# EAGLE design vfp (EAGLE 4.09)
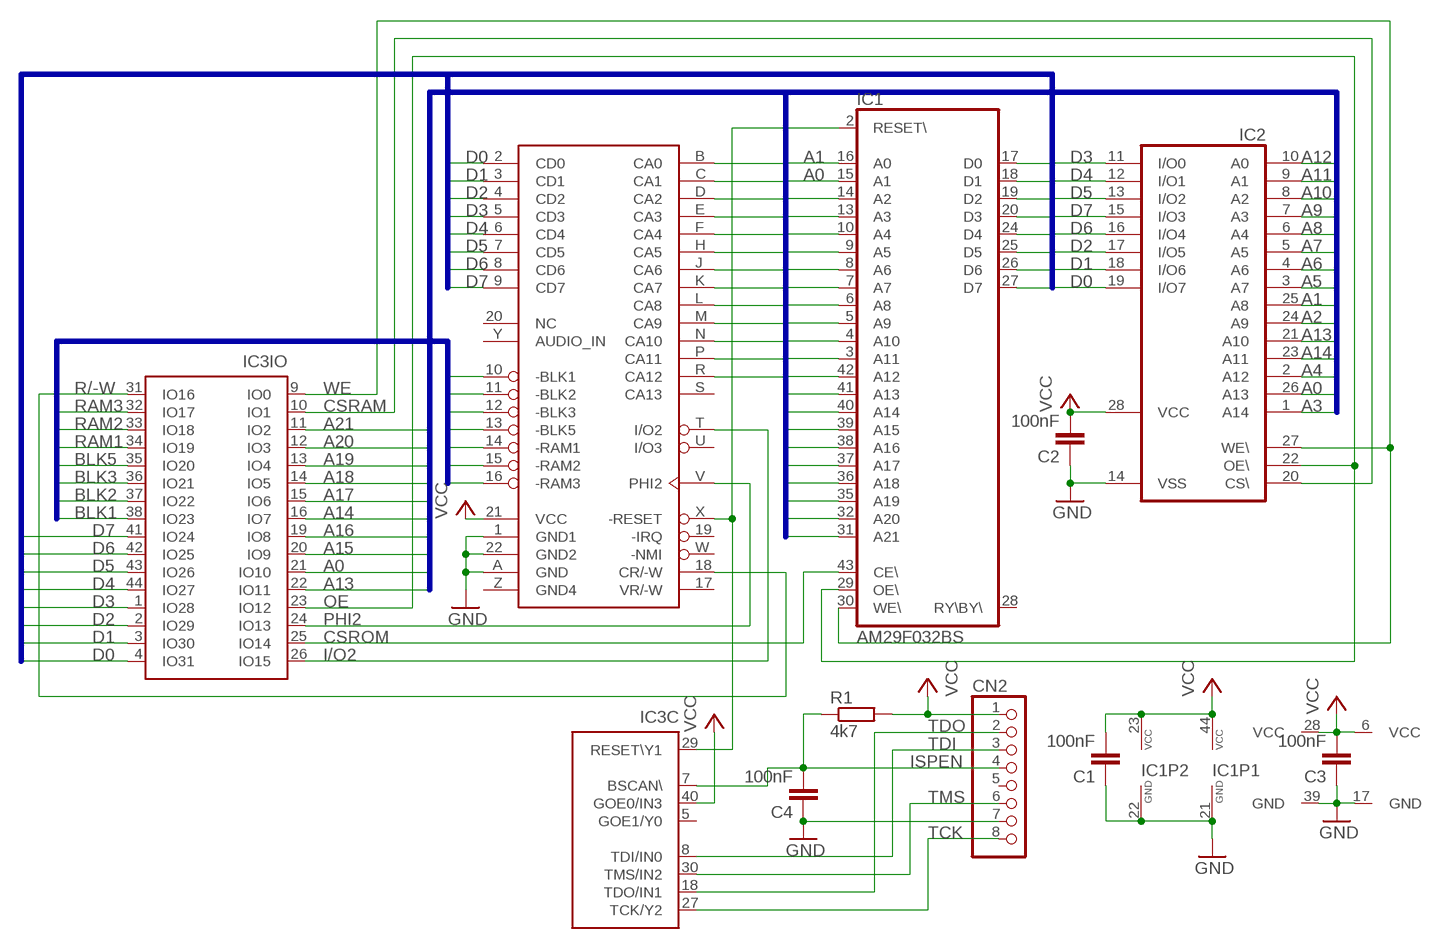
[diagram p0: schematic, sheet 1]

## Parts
C1  100nF  C-EUC0805  [C0805]
C2  100nF  C-EUC0805  [C0805]
C3  100nF  C-EUC0805  [C0805]
C4  100nF  C-EUC0805  [C0805]
CN1  VIC20CART1  [VIC20CART]
CN2  PINHD-1X8  [1X08]
IC1  AM29F032BS  [SO44]
IC2  62256FP  [SO28L]
IC3  2064VET44  [TQFP44]
R1  4k7  R-EU_R0805  [R0805]

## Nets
A0: CN1.B(CA0) IC1.15(A1) IC2.26(A13) IC3.21(IO:IO10)
A1: CN1.C(CA1) IC1.16(A0) IC2.25(A8)
A2: CN1.D(CA2) IC1.14(A2) IC2.24(A9)
A3: CN1.E(CA3) IC1.13(A3) IC2.1(A14)
A4: CN1.F(CA4) IC1.10(A4) IC2.2(A12)
A5: CN1.H(CA5) IC1.9(A5) IC2.3(A7)
A6: CN1.J(CA6) IC1.8(A6) IC2.4(A6)
A7: CN1.K(CA7) IC1.7(A7) IC2.5(A5)
A8: CN1.L(CA8) IC1.6(A8) IC2.6(A4)
A9: CN1.M(CA9) IC1.5(A9) IC2.7(A3)
A10: CN1.N(CA10) IC1.4(A10) IC2.8(A2)
A11: CN1.P(CA11) IC1.3(A11) IC2.9(A1)
A12: CN1.R(CA12) IC1.42(A12) IC2.10(A0)
A13: IC1.41(A13) IC2.21(A10) IC3.22(IO:IO11)
A14: IC1.40(A14) IC2.23(A11) IC3.16(IO:IO7)
A15: IC1.39(A15) IC3.20(IO:IO9)
A16: IC1.38(A16) IC3.19(IO:IO8)
A17: IC1.37(A17) IC3.15(IO:IO6)
A18: IC1.36(A18) IC3.14(IO:IO5)
A19: IC1.35(A19) IC3.13(IO:IO4)
A20: IC1.32(A20) IC3.12(IO:IO3)
A21: IC1.31(A21) IC3.11(IO:IO2)
BLK1: CN1.10(-BLK1) IC3.38(IO:IO23)
BLK2: CN1.11(-BLK2) IC3.37(IO:IO22)
BLK3: CN1.12(-BLK3) IC3.36(IO:IO21)
BLK5: CN1.13(-BLK5) IC3.35(IO:IO20)
CSRAM: IC2.20(CS\) IC3.10(IO:IO1)
CSROM: IC1.43(CE\) IC3.25(IO:IO14)
D0: CN1.2(CD0) IC1.17(D0) IC2.19(I/O7) IC3.4(IO:IO31)
D1: CN1.3(CD1) IC1.18(D1) IC2.18(I/O6) IC3.3(IO:IO30)
D2: CN1.4(CD2) IC1.19(D2) IC2.17(I/O5) IC3.2(IO:IO29)
D3: CN1.5(CD3) IC1.20(D3) IC2.11(I/O0) IC3.1(IO:IO28)
D4: CN1.6(CD4) IC1.24(D4) IC2.12(I/O1) IC3.44(IO:IO27)
D5: CN1.7(CD5) IC1.25(D5) IC2.13(I/O2) IC3.43(IO:IO26)
D6: CN1.8(CD6) IC1.26(D6) IC2.16(I/O4) IC3.42(IO:IO25)
D7: CN1.9(CD7) IC1.27(D7) IC2.15(I/O3) IC3.41(IO:IO24)
GND: C1.1 C2.1 C3.1 C4.1 CN1.1(GND1) CN1.22(GND2) CN1.A(GND) CN2.7 IC1.21(GND) IC1.22(GND) IC2.14(VSS) IC3.17(GND) IC3.39(GND)
I/O2: CN1.T(I/O2) IC3.26(IO:IO15)
ISPEN: C4.2 CN2.4 IC3.7(C:BSCAN\) R1.1
OE: IC1.29(OE\) IC2.22(OE\) IC3.23(IO:IO12)
PHI2: CN1.V(PHI2) IC3.24(IO:IO13)
R/-W: CN1.18(CR/-W) IC3.31(IO:IO16)
RAM1: CN1.14(-RAM1) IC3.34(IO:IO19)
RAM2: CN1.15(-RAM2) IC3.33(IO:IO18)
RAM3: CN1.16(-RAM3) IC3.32(IO:IO17)
RESET: CN1.X(-RESET) IC1.2(RESET\) IC3.29(C:RESET\Y1)
TCK: CN2.8 IC3.27(C:TCK/Y2)
TDI: CN2.3 IC3.8(C:TDI/IN0)
TDO: CN2.2 IC3.18(C:TDO/IN1)
TMS: CN2.6 IC3.30(C:TMS/IN2)
VCC: C1.2 C2.2 C3.2 CN1.21(VCC) CN2.1 IC1.23(VCC) IC1.44(VCC) IC2.28(VCC) IC3.6(V1:VCC) IC3.28(V2:VCC) IC3.40(C:GOE0/IN3) R1.2
WE: IC1.30(WE\) IC2.27(WE\) IC3.9(IO:IO0)
Unconnected: CN1.17(VR/-W) CN1.19(-IRQ) CN1.20(NC) CN1.S(CA13) CN1.U(I/O3) CN1.W(-NMI) CN1.Y(AUDIO_IN) CN1.Z(GND4) CN2.5 IC1.1(NC) IC1.28(RY\BY\) IC3.5(C:GOE1/Y0)

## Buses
A[0..21]
D[0..7]
BLK[1..3],BLK5,RAM[1..3]

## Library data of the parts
C1-C4 = rcl:C-EU: CAPACITOR, European symbol
CN1 = vic-20:VIC20CART*: VIC-20 cartridge port connector
CN2 = pinhead:PINHD-1X8: PIN HEADER
IC1 = am29-memory:AM29F032B: 32 megabit (4Mb×8) 5-volt Flash ROM
IC2 = memory-hitachi:62256FP: MEMORY
IC3 = lattice:2064VET44: LATTICE PROGRAMMABLE DEVICE
R1 = rcl:R-EU_: RESISTOR, European symbol

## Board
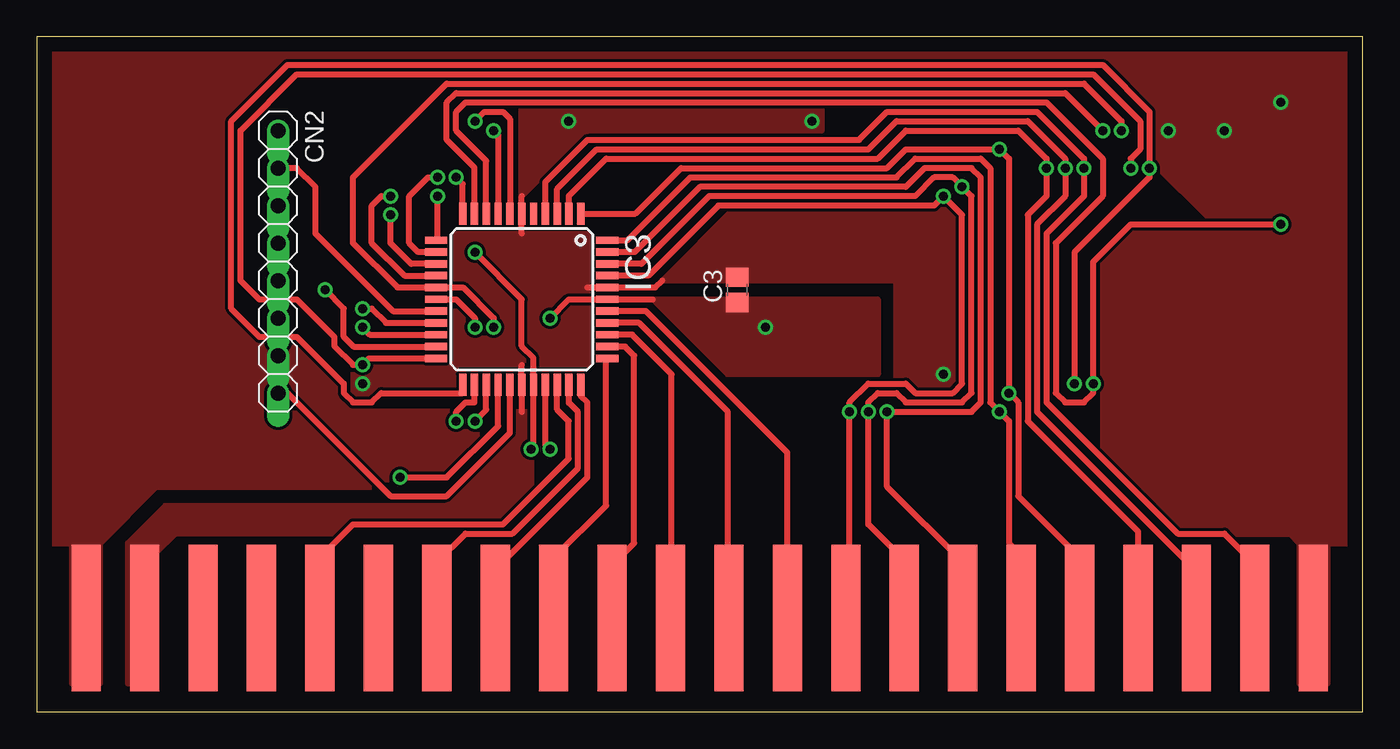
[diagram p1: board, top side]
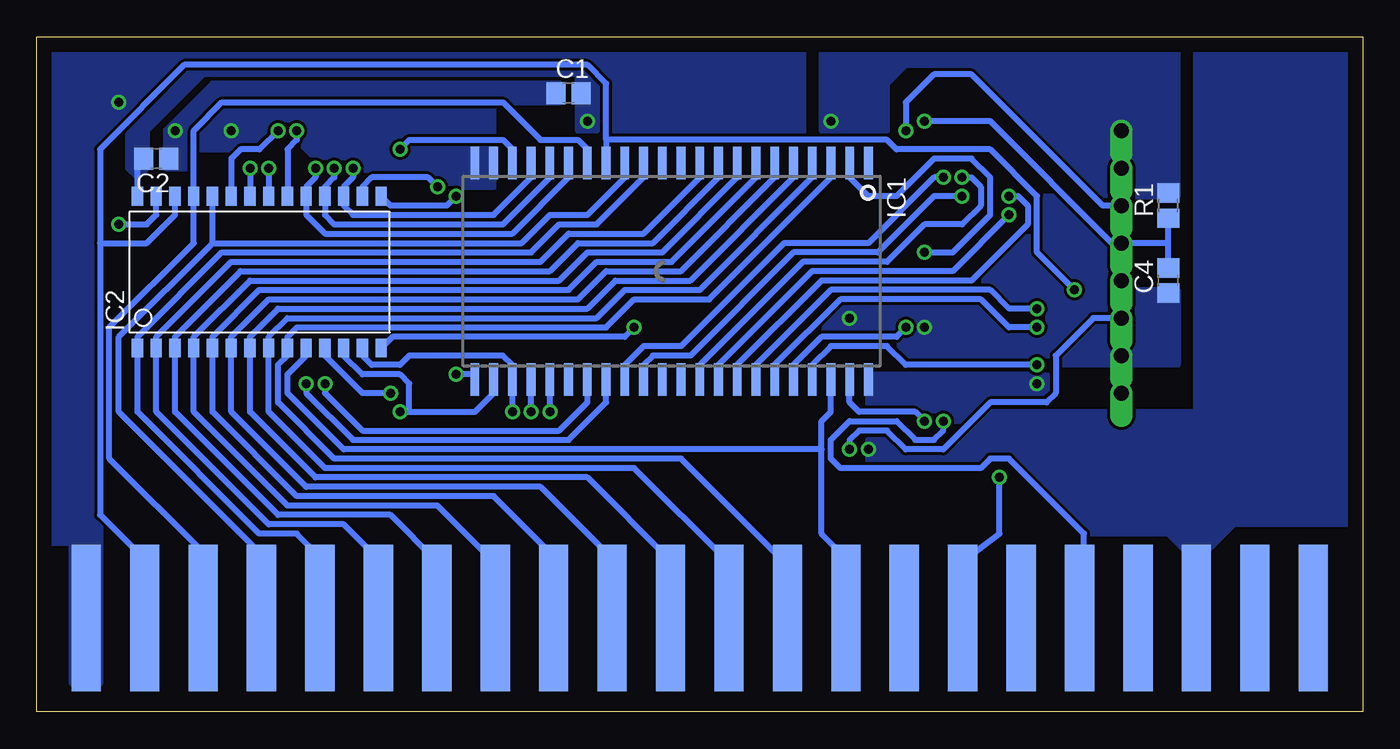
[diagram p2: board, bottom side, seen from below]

Size 89.84 x 45.71 mm. Coordinates in mm from the lower left corner, seen from the top.
Outline: 0,0 89.84,0 89.84,45.71 0,45.71 0,0
Copper layers used: Top, Bottom

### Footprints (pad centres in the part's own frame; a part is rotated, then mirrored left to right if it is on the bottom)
C0805 = smd 1.3 x 1.5: 1 -0.85,0; 2 0.85,0
VIC20CART = smd 1.98 x 9.9: 1 -41.58,0; 2 -37.62,0; 3 -33.66,0; 4 -29.7,0; 5 -25.74,0; 6 -21.78,0; 7 -17.82,0; 8 -13.86,0; 9 -9.9,0; 10 -5.94,0; 11 -1.98,0; 12 1.98,0; 13 5.94,0; 14 9.9,0; 15 13.86,0; 16 17.82,0; 17 21.78,0; 18 25.74,0; 19 29.7,0; 20 33.66,0; 21 37.62,0; 22 41.58,0 | smd 1.98 x 9.9 bottom: A -41.58,0; B -37.62,0; C -33.66,0; D -29.7,0; E -25.74,0; F -21.78,0; H -17.82,0; J -13.86,0; K -9.9,0; L -5.94,0; M -1.98,0; N 1.98,0; P 5.94,0; R 9.9,0; S 13.86,0; T 17.82,0; U 21.78,0; V 25.74,0; W 29.7,0; X 33.66,0; Y 37.62,0; Z 41.58,0
1X08 = drill 1.016 offset: 1 -8.89,0; 2 -6.35,0; 3 -3.81,0; 4 -1.27,0; 5 1.27,0; 6 3.81,0; 7 6.35,0; 8 8.89,0
SO44 = smd 0.6 x 2.2: 1 -13.335,-7.34; 2 -12.065,-7.34; 3 -10.795,-7.34; 4 -9.525,-7.34; 5 -8.255,-7.34; 6 -6.985,-7.34; 7 -5.715,-7.34; 8 -4.445,-7.34; 9 -3.175,-7.34; 10 -1.905,-7.34; 11 -0.635,-7.34; 12 0.635,-7.34; 13 1.905,-7.34; 14 3.175,-7.34; 15 4.445,-7.34; 16 5.715,-7.34; 17 6.985,-7.34; 18 8.255,-7.34; 19 9.525,-7.34; 20 10.795,-7.34; 21 12.065,-7.34; 22 13.335,-7.34; 23 13.335,7.34; 24 12.065,7.34; 25 10.795,7.34; 26 9.525,7.34; 27 8.255,7.34; 28 6.985,7.34; 29 5.715,7.34; 30 4.445,7.34; 31 3.175,7.34; 32 1.905,7.34; 33 0.635,7.34; 34 -0.635,7.34; 35 -1.905,7.34; 36 -3.175,7.34; 37 -4.445,7.34; 38 -5.715,7.34; 39 -6.985,7.34; 40 -8.255,7.34; 41 -9.525,7.34; 42 -10.795,7.34; 43 -12.065,7.34; 44 -13.335,7.34
SO28L = smd 0.762 x 1.27: 1 -7.62,-5.207; 2 -6.35,-5.207; 3 -5.08,-5.207; 4 -3.81,-5.207; 5 -2.54,-5.207; 6 -1.27,-5.207; 7 0,-5.207; 8 1.27,-5.207; 9 2.54,-5.207; 10 3.81,-5.207; 11 5.08,-5.207; 12 6.35,-5.207; 13 7.62,-5.207; 14 8.89,-5.207; 15 8.89,5.08; 16 7.62,5.08; 17 6.35,5.08; 18 5.08,5.08; 19 3.81,5.08; 20 2.54,5.08; 21 1.27,5.08; 22 0,5.08; 23 -1.27,5.08; 24 -2.54,5.08; 25 -3.81,5.08; 26 -5.08,5.08; 27 -6.35,5.08; 28 -7.62,5.08
TQFP44 = smd 1.5 x 0.5: 1 -5.8,4; 2 -5.8,3.2; 3 -5.8,2.4; 4 -5.8,1.6; 5 -5.8,0.8; 6 -5.8,0; 7 -5.8,-0.8; 8 -5.8,-1.6; 9 -5.8,-2.4; 10 -5.8,-3.2; 11 -5.8,-4; 23 5.8,-4; 24 5.8,-3.2; 25 5.8,-2.4; 26 5.8,-1.6; 27 5.8,-0.8; 28 5.8,0; 29 5.8,0.8; 30 5.8,1.6; 31 5.8,2.4; 32 5.8,3.2; 33 5.8,4 | smd 0.5 x 1.5: 12 -4,-5.8; 13 -3.2,-5.8; 14 -2.4,-5.8; 15 -1.6,-5.8; 16 -0.8,-5.8; 17 0,-5.8; 18 0.8,-5.8; 19 1.6,-5.8; 20 2.4,-5.8; 21 3.2,-5.8; 22 4,-5.8; 34 4,5.8; 35 3.2,5.8; 36 2.4,5.8; 37 1.6,5.8; 38 0.8,5.8; 39 0,5.8; 40 -0.8,5.8; 41 -1.6,5.8; 42 -2.4,5.8; 43 -3.2,5.8; 44 -4,5.8
R0805 = smd 1.3 x 1.5: 1 -0.85,0; 2 0.85,0

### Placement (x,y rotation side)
C1  53.81,41.91 0 bottom
C2  81.75,37.46 180 bottom
C3  47.46,28.57 90 top
C4  13.17,29.2 90 bottom
CN1  44.92,6.35 180 top
CN2  16.35,30.47 270 top
IC1  46.83,29.84 180 bottom
IC2  75.4,29.84 0 bottom
IC3  32.86,27.93 270 top
R1  13.17,34.29 90 bottom

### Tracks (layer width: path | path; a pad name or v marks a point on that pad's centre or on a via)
A0  (via drill 0.61)
  Top 0.406: v19.52,28.57 20.79,27.3 20.79,25.39 21.45,24.73 IC3.21
  Bottom 0.406: IC2.26 80.48,33.65 82.38,31.75 85.56,31.75 | CN1.B 82.54,10.31 85.56,13.33 85.56,31.75 | 85.56,31.75 85.56,38.1 79.84,43.81 52.54,43.81 51.27,42.54 51.27,38.73 | 51.27,38.73 IC1.15 | 51.27,38.73 32.22,38.73 31.59,38.1 25.23,38.1 22.06,34.92 22.06,31.11 v19.52,28.57
A1
  Bottom 0.406: CN1.C 78.58,10.79 84.92,17.14 84.92,26.03 79.21,31.75 IC2.25 79.21,39.37 77.3,41.27 58.26,41.27 55.72,38.73 53.18,38.73 52.54,38.1 IC1.16
A2
  Bottom 0.406: CN1.D 74.62,10.64 84.29,20.32 84.29,25.39 77.94,31.75 | 77.94,31.75 IC2.24 | IC1.14 50,36.19 52.54,33.65 55.08,33.65 56.98,31.75 77.94,31.75
A3
  Bottom 0.406: IC1.13 48.73,36.19 51.91,33.02 54.45,33.02 56.35,31.11 77.3,31.11 83.02,25.39 IC2.1 83.02,20.32 74.77,12.06 72.22,12.06 70.66,10.5 CN1.E
A4
  Bottom 0.406: CN1.F 66.7,10.34 69.05,12.7 74.13,12.7 81.75,20.32 IC2.2 81.75,25.39 76.67,30.47 55.72,30.47 53.81,32.38 48.73,32.38 44.92,36.19 IC1.10
A5
  Bottom 0.406: CN1.H 62.74,10.2 65.88,13.33 73.49,13.33 80.48,20.32 IC2.3 80.48,25.39 76.03,29.84 55.08,29.84 53.18,31.75 48.09,31.75 43.65,36.19 IC1.9
A6
  Bottom 0.406: CN1.J 58.78,10.04 62.7,13.96 72.86,13.96 79.21,20.32 IC2.4 79.21,25.39 75.4,29.2 54.45,29.2 52.54,31.11 47.46,31.11 42.38,36.19 IC1.8
A7
  Bottom 0.406: CN1.K 54.82,10.53 58.89,14.6 72.22,14.6 77.94,20.32 IC2.5 77.94,25.39 74.77,28.57 53.81,28.57 51.91,30.47 46.83,30.47 41.11,36.19 IC1.7
A8
  Bottom 0.406: CN1.L 50.86,10.38 55.72,15.23 71.59,15.23 76.67,20.32 IC2.6 76.67,25.39 74.13,27.93 53.18,27.93 51.27,29.84 46.19,29.84 39.84,36.19 IC1.6
A9
  Bottom 0.406: CN1.M 46.9,10.23 52.54,15.87 70.95,15.87 75.4,20.32 IC2.7 75.4,25.39 73.49,27.3 52.54,27.3 50.63,29.2 45.55,29.2 38.57,36.19 IC1.5
A10
  Bottom 0.406: CN1.N 42.94,10.08 49.37,16.5 70.32,16.5 74.13,20.32 IC2.8 74.13,25.39 72.86,26.66 51.91,26.66 50,28.57 44.92,28.57 37.3,36.19 IC1.4
A11
  Bottom 0.406: CN1.P 38.98,9.93 46.19,17.14 69.68,17.14 73.49,20.95 73.49,23.49 72.86,24.12 IC2.9 72.86,25.39 72.22,26.03 51.27,26.03 49.37,27.93 44.29,27.93 36.03,36.19 IC1.3
A12
  Bottom 0.406: CN1.R 35.02,10.41 36.66,12.06 36.66,17.77 | 36.66,17.77 69.05,17.77 72.86,21.59 72.86,22.86 71.59,24.12 IC2.10 | IC1.42 36.03,20.32 36.66,19.68 36.66,17.77
A13  (via drill 0.61)
  Top 0.406: v74.13,36.83 74.13,37.46 74.77,38.1 74.77,40 71.59,43.18 17.62,43.18 13.81,39.37 13.81,29.2 15.08,27.93 17.62,27.93 20.16,25.39 20.16,24.76 21.43,23.49 v22.06,23.49 22.51,23.93 IC3.22
  Bottom 0.406: v74.13,36.83 IC2.21 | IC1.41 37.3,23.49 36.03,24.76 32.22,24.76 30.95,23.49 v22.06,23.49
A14  (via drill 0.61)
  Top 0.406: v73.49,39.37 73.49,40 70.95,42.54 27.78,42.54 21.43,36.19 21.43,31.75 24.44,28.73 IC3.16 28.88,28.73 30.95,26.66 v30.95,26.03
  Bottom 0.406: IC2.23 76.67,37.46 76.03,38.1 74.77,38.1 v73.49,39.37 | v30.95,26.03 31.59,25.39 36.66,25.39 38.57,23.49 IC1.40
A15  (via drill 0.61)
  Top 0.406: IC3.20 22.55,25.54 v22.06,26.03
  Bottom 0.406: IC1.39 39.84,23.49 35.4,27.93 25.87,27.93 23.96,26.03 v22.06,26.03
A16  (via drill 0.61)
  Top 0.406: IC3.19 23.66,26.34 22.7,27.3 v22.06,27.3
  Bottom 0.406: IC1.38 41.11,23.49 36.03,28.57 25.23,28.57 23.96,27.3 v22.06,27.3
A17  (via drill 0.61)
  Top 0.406: IC3.15 24.91,29.54 22.7,31.75 22.7,34.29 23.33,34.92 v23.96,34.92
  Bottom 0.406: IC1.37 42.38,23.49 36.66,29.2 26.51,29.2 22.7,33.02 22.7,34.29 23.33,34.92 v23.96,34.92
A18  (via drill 0.61)
  Top 0.406: IC3.14 25.38,30.34 23.96,31.75 v23.96,33.65
  Bottom 0.406: IC1.36 43.65,23.49 37.3,29.84 27.78,29.84 v23.96,33.65
A19  (via drill 0.61)
  Top 0.406: IC3.13 25.85,31.13 25.23,31.75 25.23,34.92 26.51,36.19 v27.14,36.19
  Bottom 0.406: v27.14,36.19 26.51,36.19 25.87,35.55 25.87,34.29 27.14,33.02 29.68,33.02 32.22,30.47 37.94,30.47 44.92,23.49 IC1.35
A20  (via drill 0.61)
  Top 0.406: IC3.12 27.14,31.93 v27.14,34.92
  Bottom 0.406: IC1.32 48.73,23.49 48.09,24.12 45.55,24.12 38.57,31.11 32.86,31.11 29.05,34.92 v27.14,34.92
A21  (via drill 0.61)
  Top 0.406: IC3.11 28.86,35.75 v28.41,36.19
  Bottom 0.406: IC1.31 50,23.49 48.73,24.76 46.19,24.76 39.2,31.75 33.49,31.75 29.05,36.19 v28.41,36.19
BLK1
  Top 0.406: CN1.10 50.86,17.55 41.27,27.13 IC3.38
BLK2
  Top 0.406: CN1.11 46.83,6.35 46.83,20.32 40.8,26.34 IC3.37
BLK3
  Top 0.406: IC3.36 40.34,25.54 43.02,22.86 43.02,6.35 CN1.12
BLK5
  Top 0.406: CN1.13 38.98,9.93 40.48,11.43 40.48,24.12 39.87,24.73 IC3.35
CSRAM  (via drill 0.61)
  Top 0.406: v72.22,39.37 69.68,41.91 28.41,41.91 27.78,41.27 27.78,38.73 29.66,36.85 IC3.10
  Bottom 0.406: v72.22,39.37 72.22,38.73 72.86,38.1 IC2.20
CSROM  (via drill 0.61)
  Top 0.406: IC3.25 30.46,20.46 v29.68,19.68
  Bottom 0.406: IC1.43 34.76,20.95 34.12,20.32 30.32,20.32 v29.68,19.68
D0  (via drill 0.61)
  Top 0.406: CN1.2 82.54,10 80.48,12.06 77.3,12.06 68.41,20.95 68.41,32.38 70.95,34.92 v70.95,36.83 70.95,37.46 67.78,40.64 57.62,40.64 55.72,38.73 37.3,38.73 34.45,35.88 IC3.4
  Bottom 0.406: v70.95,36.83 70.95,36.19 71.59,35.55 IC2.19 71.59,33.65 70.32,32.38 57.62,32.38 53.81,36.19 IC1.17
D1  (via drill 0.61)
  Top 0.406: CN1.3 78.58,8.25 78.57,8.25 78.57,9.52 67.78,20.32 67.78,33.02 69.68,34.92 v69.68,36.83 69.68,37.46 67.14,40 58.26,40 56.35,38.1 37.94,38.1 35.26,35.41 IC3.3
  Bottom 0.406: v69.68,36.83 69.68,36.19 70.32,35.55 IC2.18 70.32,33.65 69.68,33.02 58.26,33.02 55.08,36.19 IC1.18
D2  (via drill 0.61)
  Top 0.406: CN1.4 74.62,12.21 67.14,19.68 67.14,33.65 68.41,34.92 v68.41,36.83 68.41,37.46 66.51,39.37 58.89,39.37 56.98,37.46 38.57,37.46 36.05,34.95 IC3.2
  Bottom 0.406: v68.41,36.83 68.41,36.19 69.05,35.55 IC2.17 69.05,34.29 68.41,33.65 58.89,33.65 56.35,36.19 IC1.19
D3  (via drill 0.61)
  Top 0.406: CN1.5 70.66,10.45 66.51,14.6 66.51,20.95 v65.88,21.59 65.88,37.46 v65.24,38.1 58.89,38.1 57.62,36.83 43.65,36.83 40.56,33.73 IC3.1
  Bottom 0.406: IC2.11 70.32,24.12 67.78,21.59 v65.88,21.59 | IC1.20 57.62,38.1 58.26,38.73 64.6,38.73 v65.24,38.1
D4  (via drill 0.61)
  Top 0.406: CN1.6 66.51,6.35 66.51,10.79 65.88,11.43 65.88,19.68 v65.24,20.32 64.6,20.95 64.6,36.83 63.97,37.46 59.52,37.46 58.26,36.19 44.29,36.19 40.03,31.93 IC3.44
  Bottom 0.406: IC1.24 58.89,21.59 60.16,20.32 64.6,20.32 | IC2.12 69.05,24.12 67.78,22.86 65.24,22.86 64.6,22.22 64.6,20.32 | v65.24,20.32 64.6,20.32
D5  (via drill 0.61)
  Top 0.406: CN1.7 62.74,10.12 57.62,15.23 v57.62,20.32 63.34,20.32 63.97,20.95 63.97,36.19 63.34,36.83 60.16,36.83 58.89,35.55 44.92,35.55 40.5,31.13 IC3.43
  Bottom 0.406: v57.62,20.32 IC1.25 57.62,23.49 58.26,24.12 64.6,24.12 65.24,23.49 67.14,23.49 67.78,24.12 IC2.13
D6  (via drill 0.61)
  Top 0.406: CN1.8 58.78,10.04 58.89,10.16 56.35,12.7 v56.35,20.32 56.35,20.95 56.98,21.59 58.26,21.59 58.89,20.95 62.7,20.95 63.34,21.59 63.34,34.92 v62.7,35.55 62.06,36.19 60.8,36.19 59.52,34.92 45.55,34.92 40.97,30.34 IC3.42
  Bottom 0.406: v62.7,35.55 63.34,36.19 67.14,36.19 67.78,35.55 IC2.16 | v56.35,20.32 IC1.26
D7  (via drill 0.61)
  Top 0.406: CN1.9 54.82,9.89 | 54.82,9.89 55.08,10.16 v55.08,20.32 55.08,20.95 56.35,22.22 58.89,22.22 59.52,21.59 62.06,21.59 62.7,22.22 62.7,33.65 v61.43,34.92 60.8,34.29 46.19,34.29 41.44,29.54 IC3.41 | 54.82,9.89 54.82,10.41
  Bottom 0.406: v61.43,34.92 62.06,34.29 65.88,34.29 IC2.15 | v55.08,20.32 IC1.27
GND  (via drill 0.61)
  Top 0.406: 41.74,27.93 IC3.39 36.03,27.93 v34.76,26.66 | IC3.17 28.41,27.93 29.68,26.66 v29.68,26.03
  Bottom 0.406: IC2.14 65.75,25.39 50,25.39 v49.37,26.03
  other vias: 80.48,39.37 76.67,39.37 84.29,41.27
  pour Top (no thermals): 85.56,1.9 87.46,1.9 87.46,11.43 89.37,11.43 89.37,45.72 0.47,45.72 0.47,11.43 2.38,11.43 2.38,1.9 4.28,1.9 4.28,11.43 8.09,15.23 27.14,15.23 30.95,19.05 30.95,20.32 21.43,20.32 20.79,20.95 20.79,29.2 23.33,29.2 23.33,38.1 29.05,43.81 72.86,43.81 75.4,41.27 75.4,37.46 79.84,33.02 72.22,33.02 72.22,12.06 84.92,12.06 85.56,11.43
  pour Bottom (no thermals): 54.45,42.54 77.94,42.54 81.11,39.37 81.11,36.83 79.21,36.83 79.21,38.1 76.67,38.1 76.03,38.73 72.22,38.73 69.05,35.55 58.89,35.55 58.89,41.27 54.45,41.27
  pour Top (no thermals): 41.74,27.93 56.98,27.93 56.98,22.86 46.83,22.86
  pour Bottom (no thermals): 15.71,28.57 12.54,28.57 12.54,23.49 38.57,23.49 38.57,34.29 32.22,34.29 32.22,38.1 50.63,38.1 50.63,42.54 52.54,44.45 79.84,44.45 85.56,38.73 85.56,1.9 87.46,1.9 87.46,11.43 89.37,11.43 89.37,45.72 37.94,45.72 37.94,38.73 26.51,38.73 22.7,34.92 20.79,34.92 20.16,34.29 16.35,34.29 16.35,29.2
I/O2  (via drill 0.61)
  Top 0.406: v24.6,15.87 27.78,15.87 31.26,19.35 IC3.26
  Bottom 0.406: CN1.T 27.1,10.2 24.6,12.06 v24.6,15.87
ISPEN  (via drill 0.61)
  Top 0.406: IC3.7 32.05,40.17 31.59,40.64 30.32,40.64 v29.68,40
  Bottom 0.406: 13.17,31.75 CN2.4 16.98,31.75 25.23,40 v29.68,40 | 13.17,31.75 R1.1 | C4.2 13.17,31.75
OE  (via drill 0.61)
  Top 0.406: v70.32,22.22 70.32,31.11 75.4,36.19 v75.4,36.83 75.4,40.64 72.22,43.81 16.98,43.81 13.17,40 13.17,27.3 15.08,25.39 17.62,25.39 20.79,22.22 20.79,21.59 21.43,20.95 22.7,20.95 23.33,21.59 28.86,21.59 IC3.23
  Bottom 0.406: v75.4,36.83 IC2.22 | IC1.29 52.54,20.95 54.45,19.05 67.78,19.05 70.32,21.59 v70.32,22.22
PHI2  (via drill 0.61)
  Top 0.406: IC3.24 29.66,20.95 29.05,20.95 28.41,20.32 v28.41,19.68
  Bottom 0.406: CN1.V 18.89,6.35 18.89,12.06 23.96,17.14 25.23,17.14 25.87,16.5 35.4,16.5 36.03,17.14 36.03,18.41 34.76,19.68 31.59,19.68 30.32,18.41 29.05,18.41 28.41,19.05 v28.41,19.68
R/-W
  Top 0.406: CN1.18 18.89,6.35 18.89,10.16 21.43,12.7 31.59,12.7 36.03,17.14 36.03,19.68 35.26,20.46 IC3.31
RAM1
  Top 0.406: IC3.34 38.57,23.93 38.57,13.96 35.02,10.41 CN1.14
RAM2
  Top 0.406: CN1.15 31.06,9.63 37.3,15.87 37.3,20.95 36.86,21.39 IC3.33
RAM3
  Top 0.406: CN1.16 27.1,10.12 29.05,12.06 32.22,12.06 36.66,16.5 36.66,20.32 36.05,20.93 IC3.32
RESET  (via drill 0.61)
  Top 0.406: v29.68,31.11 32.86,27.93 32.86,24.76 33.66,23.96 IC3.29 33.66,17.94 v33.49,17.77
  Bottom 0.406: v29.68,31.11 27.78,31.11 25.23,33.65 25.23,36.19 26.51,37.46 29.05,37.46 31.59,34.92 33.49,34.92 34.76,36.19 IC1.2
  pour Bottom (no thermals): 33.49,15.23 33.49,18.41 27.14,18.41 25.23,20.32 11.27,20.32 11.27,45.72 0.47,45.72 0.47,12.7 8.73,12.7 10.63,10.79 10.63,1.9 11.9,1.9 11.9,10.79 13.17,12.06 24.6,12.06 24.6,15.23
TCK
  Top 0.406: CN2.8 16.98,21.59 23.96,14.6 27.78,14.6 32.05,18.88 IC3.27
TDI  (via drill 0.61)
  Top 0.406: IC3.8 31.26,39.06 v30.95,39.37
  Bottom 0.406: v30.95,39.37 30.95,41.27 29.05,43.18 26.51,43.18 17.62,34.29 CN2.3
TDO
  Top 0.406: CN2.2 17.62,36.83 18.89,35.55 18.89,32.38 24.13,27.13 IC3.18
TMS  (via drill 0.61)
  Top 0.406: IC3.30 34.45,18.08 v34.76,17.77
  Bottom 0.406: CN2.6 18.25,26.66 20.79,24.12 20.79,21.59 21.43,20.95 25.23,20.95 28.41,17.77 30.95,17.77 32.22,19.05 34.12,19.05 34.76,18.41 v34.76,17.77
VCC  (via drill 0.61)
  Top 0.406: 32.86,20.32 IC3.28 32.86,23.49 | 42.38,29.2 41.91,28.73 IC3.40 37.3,28.73 | 32.86,34.92 IC3.6 32.86,32.38
  Bottom 0.406: C2.2 83.02,36.83 IC2.28 | IC1.23 60.16,22.86 v61.43,22.86
  other vias: 36.03,40 52.54,40 22.06,22.22
  pour Top (no thermals): 8.09,1.9 6.18,1.9 6.18,11.43 8.73,13.96 27.78,13.96 32.22,18.41 32.22,20.32 33.49,20.32 33.49,12.06 9.36,12.06 8.09,10.79
  pour Bottom (no thermals): 51.91,42.54 51.91,39.37 53.18,39.37 53.18,43.18 78.57,43.18 82.38,39.37 82.38,36.83 83.02,36.19 83.65,36.83 83.65,39.37 79.21,43.81 53.18,43.81
  pour Bottom (no thermals): 12.54,34.92 12.54,45.72 36.66,45.72 36.66,39.37 32.22,39.37 32.22,42.54 30.95,43.81 26.51,43.81 17.62,34.92
  pour Top (no thermals): 42.38,29.2 47.46,34.29 63.34,34.29 63.34,21.59 58.26,21.59 58.26,29.2
  pour Top (no thermals): 32.86,41.27 53.18,41.27 53.18,39.37 37.3,39.37 32.86,34.92
  pour Top: 28.41,32.38 37.3,32.38 37.3,23.49 33.49,23.49 32.86,24.12 32.86,23.49 28.41,23.49
  pour Top: 28.41,23.49 21.43,23.49 21.43,21.59 22.06,20.95 28.41,20.95
  pour Bottom (no thermals): 33.49,22.86 21.43,22.86 21.43,21.59 25.23,21.59 27.14,19.68 33.49,19.68
WE  (via drill 0.61)
  Top 0.406: v84.29,33.02 74.13,33.02 71.59,30.47 v71.59,22.22 71.59,21.59 70.95,20.95 69.68,20.95 69.05,21.59 69.05,31.75 72.22,34.92 72.22,37.46 68.41,41.27 29.05,41.27 28.41,40.64 28.41,39.37 30.46,37.32 IC3.9
  Bottom 0.406: v84.29,33.02 82.38,33.02 81.75,33.65 IC2.27 | IC1.30 51.27,20.95 53.81,18.41 68.41,18.41 71.59,21.59 v71.59,22.22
